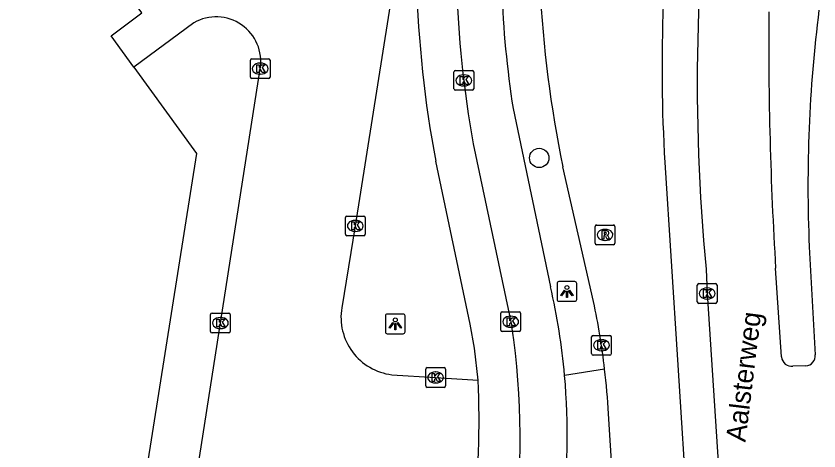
# Model space of a CAD drawing. Extents: x 161094 to 161705, y 379509 to 380907.
# Drawn here: x 161646.2 to 161686.89, y 380754.87 to 380776.91 of the extents above; entities that cross this region are included whole.
import ezdxf

# ---------------------------------------------------------------- set-up
doc = ezdxf.new("R2010")
doc.units = 0
for name, color, linetype in [('IMGEO_Boom', 7, 'Continuous'), ('IMGEO_Fietspad_gesloten', 7, 'Continuous'), ('IMGEO_Kolk', 7, 'Continuous'), ('IMGEO_Lichtpunt', 7, 'Continuous'), ('IMGEO_Openbare_ruimte_label', 7, 'Continuous'), ('IMGEO_OVBaan_gesloten', 7, 'Continuous'), ('IMGEO_Pand', 7, 'Continuous'), ('IMGEO_Rijbaan_lokaal_open', 7, 'Continuous'), ('IMGEO_Rijbaan_regionaal_gesloten', 7, 'Continuous'), ('IMGEO_Rioolput', 7, 'Continuous'), ('IMGEO_Voetpad_open', 7, 'Continuous')]:
    doc.layers.add(name, color=color, linetype=linetype)

msp = doc.modelspace()

# ---------------------------------------------------------------- linework, layer by layer
at = {"layer": 'IMGEO_Boom'}
msp.add_circle((161672.711, 380769.715), 0.489, dxfattribs=at)
at = {"layer": 'IMGEO_Fietspad_gesloten'}
for points in [[(161671.386, 380772.223), (161673.279, 380763.191)], [(161669.37, 380770.437), (161671.328, 380761.181)]]:
    msp.add_lwpolyline(points, dxfattribs=at)
for centre, radius, start, end in [((161723.373, 380780.209), 54.88, 173.1036, 190.2571), ((161721.642, 380780.053), 50.862, 175.2018, 188.8552), ((161641.134, 380755.741), 32.997, 5.1467, 13.0487), ((161633.879, 380755.588), 37.865, 351.9368, 8.4941)]:
    msp.add_arc(centre, radius, start, end, dxfattribs=at)
at = {"layer": 'IMGEO_Kolk'}
for p, q in [((161658.072, 380773.816), (161658.072, 380774.668)), ((161658.147, 380774.742), (161658.999, 380774.742)), ((161659.073, 380774.668), (161659.073, 380773.816)), ((161658.56, 380774.522), (161658.585, 380774.522)), ((161658.583, 380773.962), (161658.558, 380773.962)), ((161668.392, 380773.22), (161668.392, 380774.072)), ((161668.467, 380774.146), (161669.319, 380774.146)), ((161668.88, 380773.926), (161668.905, 380773.926)), ((161669.393, 380774.072), (161669.393, 380773.22)), ((161658.999, 380773.742), (161658.147, 380773.742)), ((161668.903, 380773.366), (161668.878, 380773.366)), ((161669.319, 380773.146), (161668.467, 380773.146)), ((161662.889, 380765.848), (161662.889, 380766.7)), ((161662.964, 380766.774), (161663.816, 380766.774)), ((161663.377, 380766.554), (161663.402, 380766.554)), ((161663.89, 380766.7), (161663.89, 380765.848)), ((161663.816, 380765.774), (161662.964, 380765.774)), ((161663.4, 380765.994), (161663.375, 380765.994)), ((161680.721, 380762.422), (161680.721, 380763.274)), ((161680.796, 380763.348), (161681.648, 380763.348)), ((161681.722, 380763.274), (161681.722, 380762.422)), ((161681.209, 380763.128), (161681.234, 380763.128)), ((161681.232, 380762.568), (161681.207, 380762.568)), ((161681.648, 380762.348), (161680.796, 380762.348)), ((161656.054, 380760.926), (161656.054, 380761.778)), ((161656.129, 380761.852), (161656.981, 380761.852)), ((161656.542, 380761.632), (161656.567, 380761.632)), ((161657.055, 380761.778), (161657.055, 380760.926)), ((161670.764, 380760.992), (161670.764, 380761.844)), ((161670.839, 380761.918), (161671.691, 380761.918)), ((161671.252, 380761.698), (161671.277, 380761.698)), ((161671.765, 380761.844), (161671.765, 380760.992)), ((161671.275, 380761.138), (161671.25, 380761.138)), ((161656.981, 380760.852), (161656.129, 380760.852)), ((161656.565, 380761.072), (161656.54, 380761.072)), ((161671.691, 380760.918), (161670.839, 380760.918)), ((161675.439, 380760.727), (161676.291, 380760.727)), ((161675.364, 380759.801), (161675.364, 380760.653)), ((161675.852, 380760.507), (161675.877, 380760.507)), ((161676.365, 380760.653), (161676.365, 380759.801)), ((161675.875, 380759.947), (161675.85, 380759.947)), ((161676.291, 380759.727), (161675.439, 380759.727)), ((161666.961, 380758.168), (161666.961, 380759.02)), ((161667.036, 380759.094), (161667.888, 380759.094)), ((161667.449, 380758.874), (161667.474, 380758.874)), ((161667.962, 380759.02), (161667.962, 380758.168)), ((161667.472, 380758.314), (161667.447, 380758.314)), ((161667.888, 380758.094), (161667.036, 380758.094))]:
    msp.add_line(p, q, dxfattribs=at)
for points in [[(161658.072, 380773.816), (161658.072, 380774.668)], [(161658.147, 380774.742), (161658.999, 380774.742)], [(161659.073, 380774.668), (161659.073, 380773.816)], [(161658.393, 380774.442), (161658.516, 380774.442), (161658.516, 380774.291), (161658.646, 380774.442), (161658.81, 380774.442), (161658.664, 380774.291), (161658.817, 380774.042), (161658.665, 380774.042), (161658.58, 380774.206), (161658.516, 380774.139), (161658.516, 380774.042), (161658.393, 380774.042), (161658.393, 380774.442)], [(161668.392, 380773.22), (161668.392, 380774.072)], [(161668.467, 380774.146), (161669.319, 380774.146)], [(161668.713, 380773.846), (161668.836, 380773.846), (161668.836, 380773.695), (161668.966, 380773.846), (161669.13, 380773.846), (161668.984, 380773.695), (161669.137, 380773.446), (161668.985, 380773.446), (161668.9, 380773.61), (161668.836, 380773.543), (161668.836, 380773.446), (161668.713, 380773.446), (161668.713, 380773.846)], [(161669.393, 380774.072), (161669.393, 380773.22)], [(161658.999, 380773.742), (161658.147, 380773.742)], [(161669.319, 380773.146), (161668.467, 380773.146)], [(161662.889, 380765.848), (161662.889, 380766.7)], [(161662.964, 380766.774), (161663.816, 380766.774)], [(161663.21, 380766.474), (161663.333, 380766.474), (161663.333, 380766.323), (161663.463, 380766.474), (161663.627, 380766.474), (161663.481, 380766.323), (161663.634, 380766.074), (161663.482, 380766.074), (161663.397, 380766.238), (161663.333, 380766.171), (161663.333, 380766.074), (161663.21, 380766.074), (161663.21, 380766.474)], [(161663.89, 380766.7), (161663.89, 380765.848)], [(161663.816, 380765.774), (161662.964, 380765.774)], [(161680.721, 380762.422), (161680.721, 380763.274)], [(161680.796, 380763.348), (161681.648, 380763.348)], [(161681.722, 380763.274), (161681.722, 380762.422)], [(161681.042, 380763.048), (161681.165, 380763.048), (161681.165, 380762.897), (161681.295, 380763.048), (161681.459, 380763.048), (161681.313, 380762.897), (161681.466, 380762.648), (161681.314, 380762.648), (161681.229, 380762.812), (161681.165, 380762.745), (161681.165, 380762.648), (161681.042, 380762.648), (161681.042, 380763.048)], [(161681.648, 380762.348), (161680.796, 380762.348)], [(161656.054, 380760.926), (161656.054, 380761.778)], [(161656.129, 380761.852), (161656.981, 380761.852)], [(161656.375, 380761.552), (161656.498, 380761.552), (161656.498, 380761.401), (161656.628, 380761.552), (161656.792, 380761.552), (161656.646, 380761.401), (161656.799, 380761.152), (161656.647, 380761.152), (161656.562, 380761.316), (161656.498, 380761.249), (161656.498, 380761.152), (161656.375, 380761.152), (161656.375, 380761.552)], [(161657.055, 380761.778), (161657.055, 380760.926)], [(161670.764, 380760.992), (161670.764, 380761.844)], [(161670.839, 380761.918), (161671.691, 380761.918)], [(161671.085, 380761.618), (161671.208, 380761.618), (161671.208, 380761.467), (161671.338, 380761.618), (161671.502, 380761.618), (161671.356, 380761.467), (161671.509, 380761.218), (161671.357, 380761.218), (161671.272, 380761.382), (161671.208, 380761.315), (161671.208, 380761.218), (161671.085, 380761.218), (161671.085, 380761.618)], [(161671.765, 380761.844), (161671.765, 380760.992)], [(161656.981, 380760.852), (161656.129, 380760.852)], [(161671.691, 380760.918), (161670.839, 380760.918)], [(161675.439, 380760.727), (161676.291, 380760.727)], [(161675.364, 380759.801), (161675.364, 380760.653)], [(161675.685, 380760.427), (161675.808, 380760.427), (161675.808, 380760.276), (161675.938, 380760.427), (161676.102, 380760.427), (161675.956, 380760.276), (161676.109, 380760.027), (161675.957, 380760.027), (161675.872, 380760.191), (161675.808, 380760.124), (161675.808, 380760.027), (161675.685, 380760.027), (161675.685, 380760.427)], [(161676.365, 380760.653), (161676.365, 380759.801)], [(161676.291, 380759.727), (161675.439, 380759.727)], [(161666.961, 380758.168), (161666.961, 380759.02)], [(161667.036, 380759.094), (161667.888, 380759.094)], [(161667.282, 380758.794), (161667.405, 380758.794), (161667.405, 380758.643), (161667.535, 380758.794), (161667.699, 380758.794), (161667.553, 380758.643), (161667.706, 380758.394), (161667.554, 380758.394), (161667.469, 380758.558), (161667.405, 380758.491), (161667.405, 380758.394), (161667.282, 380758.394), (161667.282, 380758.794)], [(161667.962, 380759.02), (161667.962, 380758.168)], [(161667.888, 380758.094), (161667.036, 380758.094)]]:
    msp.add_lwpolyline(points, dxfattribs=at)
for centre, start, end in [((161658.149, 380774.666), 91.552, 178.448), ((161658.149, 380774.666), 91.552, 178.448), ((161658.997, 380774.666), 1.552, 88.448), ((161658.997, 380774.666), 1.552, 88.448), ((161658.149, 380773.818), 181.552, 268.448), ((161658.149, 380773.818), 181.552, 268.448), ((161658.997, 380773.818), 271.552, 358.448), ((161658.997, 380773.818), 271.552, 358.448), ((161668.469, 380774.07), 91.552, 178.448), ((161668.469, 380774.07), 91.552, 178.448), ((161669.317, 380774.07), 1.552, 88.448), ((161669.317, 380774.07), 1.552, 88.448), ((161668.469, 380773.222), 181.552, 268.448), ((161668.469, 380773.222), 181.552, 268.448), ((161669.317, 380773.222), 271.552, 358.448), ((161669.317, 380773.222), 271.552, 358.448), ((161662.966, 380766.698), 91.552, 178.448), ((161662.966, 380766.698), 91.552, 178.448), ((161663.814, 380766.698), 1.552, 88.448), ((161663.814, 380766.698), 1.552, 88.448), ((161662.966, 380765.85), 181.552, 268.448), ((161662.966, 380765.85), 181.552, 268.448), ((161663.814, 380765.85), 271.552, 358.448), ((161663.814, 380765.85), 271.552, 358.448), ((161680.798, 380763.272), 91.552, 178.448), ((161680.798, 380763.272), 91.552, 178.448), ((161681.646, 380763.272), 1.552, 88.448), ((161681.646, 380763.272), 1.552, 88.448), ((161680.798, 380762.424), 181.552, 268.448), ((161680.798, 380762.424), 181.552, 268.448), ((161681.646, 380762.424), 271.552, 358.448), ((161681.646, 380762.424), 271.552, 358.448), ((161656.131, 380761.776), 91.552, 178.448), ((161656.131, 380761.776), 91.552, 178.448), ((161656.979, 380761.776), 1.552, 88.448), ((161656.979, 380761.776), 1.552, 88.448), ((161670.841, 380761.842), 91.552, 178.448), ((161670.841, 380761.842), 91.552, 178.448), ((161671.689, 380761.842), 1.552, 88.448), ((161671.689, 380761.842), 1.552, 88.448), ((161656.131, 380760.928), 181.552, 268.448), ((161656.131, 380760.928), 181.552, 268.448), ((161656.979, 380760.928), 271.552, 358.448), ((161656.979, 380760.928), 271.552, 358.448), ((161670.841, 380760.994), 181.552, 268.448), ((161670.841, 380760.994), 181.552, 268.448), ((161671.689, 380760.994), 271.552, 358.448), ((161671.689, 380760.994), 271.552, 358.448), ((161675.441, 380760.651), 91.552, 178.448), ((161675.441, 380760.651), 91.552, 178.448), ((161676.289, 380760.651), 1.552, 88.448), ((161676.289, 380760.651), 1.552, 88.448), ((161675.441, 380759.803), 181.552, 268.448), ((161675.441, 380759.803), 181.552, 268.448), ((161676.289, 380759.803), 271.552, 358.448), ((161676.289, 380759.803), 271.552, 358.448), ((161667.038, 380759.018), 91.552, 178.448), ((161667.038, 380759.018), 91.552, 178.448), ((161667.886, 380759.018), 1.552, 88.448), ((161667.886, 380759.018), 1.552, 88.448), ((161667.038, 380758.17), 181.552, 268.448), ((161667.038, 380758.17), 181.552, 268.448), ((161667.886, 380758.17), 271.552, 358.448), ((161667.886, 380758.17), 271.552, 358.448)]:
    msp.add_arc(centre, 0.0765, start, end, dxfattribs=at)
for centre, major_axis, ratio, start_param, end_param in [((161658.559, 380774.242), (-0.387, 0.002), 0.722429, 4.712389, 7.853982), ((161658.584, 380774.242), (-0.39, 0.002), 0.717154, 1.570796, 4.712389), ((161668.879, 380773.646), (-0.387, 0.002), 0.722429, 4.712389, 7.853982), ((161668.904, 380773.646), (-0.39, 0.002), 0.717154, 1.570796, 4.712389), ((161663.376, 380766.274), (-0.387, 0.002), 0.722429, 4.712389, 7.853982), ((161663.401, 380766.274), (-0.39, 0.002), 0.717154, 1.570796, 4.712389), ((161681.208, 380762.848), (-0.387, 0.002), 0.722429, 4.712389, 7.853982), ((161681.233, 380762.848), (-0.39, 0.002), 0.717154, 1.570796, 4.712389), ((161656.541, 380761.352), (-0.387, 0.002), 0.722429, 4.712389, 7.853982), ((161656.566, 380761.352), (-0.39, 0.002), 0.717154, 1.570796, 4.712389), ((161671.251, 380761.418), (-0.387, 0.002), 0.722429, 4.712389, 7.853982), ((161671.276, 380761.418), (-0.39, 0.002), 0.717154, 1.570796, 4.712389), ((161675.851, 380760.227), (-0.387, 0.002), 0.722429, 4.712389, 7.853982), ((161675.876, 380760.227), (-0.39, 0.002), 0.717154, 1.570796, 4.712389), ((161667.448, 380758.594), (-0.387, 0.002), 0.722429, 4.712389, 7.853982), ((161667.473, 380758.594), (-0.39, 0.002), 0.717154, 1.570796, 4.712389)]:
    msp.add_ellipse(centre, major_axis=major_axis, ratio=ratio, start_param=start_param, end_param=end_param, dxfattribs=at)
at = {"layer": 'IMGEO_Lichtpunt'}
for p, q in [((161673.615, 380763.354), (161673.615, 380762.547)), ((161673.615, 380763.354), (161673.615, 380762.547)), ((161674.517, 380763.449), (161673.709, 380763.449)), ((161674.517, 380763.449), (161673.709, 380763.449)), ((161674.611, 380762.547), (161674.611, 380763.354)), ((161674.611, 380762.547), (161674.611, 380763.354)), ((161673.709, 380762.453), (161674.517, 380762.453)), ((161673.709, 380762.453), (161674.517, 380762.453)), ((161664.919, 380761.712), (161664.919, 380760.905)), ((161664.919, 380761.712), (161664.919, 380760.905)), ((161665.821, 380761.807), (161665.013, 380761.807)), ((161665.821, 380761.807), (161665.013, 380761.807)), ((161665.915, 380760.905), (161665.915, 380761.712)), ((161665.915, 380760.905), (161665.915, 380761.712)), ((161665.013, 380760.811), (161665.821, 380760.811)), ((161665.013, 380760.811), (161665.821, 380760.811))]:
    msp.add_line(p, q, dxfattribs=at)
for points in [[(161673.989, 380763.018), (161674.028, 380762.99), (161673.84, 380762.728), (161673.802, 380762.755), (161673.989, 380763.018)], [(161674.091, 380762.97), (161674.138, 380762.97), (161674.138, 380762.648), (161674.091, 380762.648), (161674.091, 380762.97)], [(161674.201, 380762.99), (161674.239, 380763.017), (161674.426, 380762.755), (161674.387, 380762.727), (161674.201, 380762.99)], [(161665.293, 380761.376), (161665.332, 380761.348), (161665.144, 380761.086), (161665.106, 380761.113), (161665.293, 380761.376)], [(161665.395, 380761.328), (161665.442, 380761.328), (161665.442, 380761.006), (161665.395, 380761.006), (161665.395, 380761.328)], [(161665.505, 380761.348), (161665.543, 380761.375), (161665.73, 380761.113), (161665.691, 380761.085), (161665.505, 380761.348)]]:
    msp.add_lwpolyline(points, dxfattribs=at)
for centre in [(161674.114, 380763.152), (161665.418, 380761.51)]:
    msp.add_circle(centre, 0.0994, dxfattribs=at)
for centre, start, end in [((161673.709, 380763.354), 90, 180), ((161673.709, 380763.354), 90, 180), ((161674.517, 380763.354), 0, 90), ((161674.517, 380763.354), 0, 90), ((161673.709, 380762.547), 180, 270), ((161673.709, 380762.547), 180, 270), ((161674.517, 380762.547), 270, 0), ((161674.517, 380762.547), 270, 360), ((161665.013, 380761.712), 90, 180), ((161665.013, 380761.712), 90, 180), ((161665.821, 380761.712), 0, 90), ((161665.821, 380761.712), 0, 90), ((161665.013, 380760.905), 180, 270), ((161665.013, 380760.905), 180, 270), ((161665.821, 380760.905), 270, 0), ((161665.821, 380760.905), 270, 360)]:
    msp.add_arc(centre, 0.0946, start, end, dxfattribs=at)
at = {"layer": 'IMGEO_OVBaan_gesloten'}
for points in [[(161679.076, 380769.48), (161679.713, 380759.482), (161680.24, 380751.239)], [(161675.461, 380762.437), (161673.908, 380769.269)], [(161676.761, 380747.77), (161676.717, 380749.003), (161676.218, 380756.754)]]:
    msp.add_lwpolyline(points, dxfattribs=at)
for centre, radius, start, end in [((161760.684, 380774.29), 81.75, 172.12146, 183.37333), ((161732.697, 380781.403), 60.028, 182.86621, 191.66173), ((161640.216, 380754.852), 36.052, 6.6276, 12.1451), ((161639.684, 380754.803), 36.586, 3.0574, 6.6084)]:
    msp.add_arc(centre, radius, start, end, dxfattribs=at)
at = {"layer": 'IMGEO_Pand'}
for points in [[(161652.167, 380774.32), (161651.017, 380775.909), (161652.573, 380777.061), (161651.743, 380778.194), (161652.429, 380778.714), (161650.668, 380781.143), (161649.954, 380780.648), (161649.119, 380781.768), (161647.581, 380780.621), (161646.411, 380782.235)], [(161652.167, 380774.32), (161655.336, 380769.945), (161652.191, 380750), (161651.629, 380746.437), (161648.267, 380746.956), (161647.471, 380741.727), (161647.355, 380741.635), (161645.817, 380741.887)]]:
    msp.add_lwpolyline(points, dxfattribs=at)
at = {"layer": 'IMGEO_Rijbaan_lokaal_open'}
for points in [[(161665.659, 380780.797), (161665.645, 380780.589), (161663.39, 380766.274), (161662.705, 380762.13)], [(161655.209, 380776.564), (161652.167, 380774.32)], [(161654.446, 380747.932), (161654.778, 380750), (161658.575, 380774.236)], [(161665.24, 380758.734), (161667.462, 380758.594), (161669.617, 380758.465)], [(161676.027, 380759.013), (161673.998, 380758.701)]]:
    msp.add_lwpolyline(points, dxfattribs=at)
for centre, radius, start, end in [((161656.334, 380774.593), 2.27, 350.9594, 119.7034), ((161665.598, 380761.646), 2.933, 170.4933, 262.9869), ((161641.27, 380755.754), 32.86, 352.1827, 5.1446), ((161620.619, 380756.365), 49.043, 353.974, 2.4546)]:
    msp.add_arc(centre, radius, start, end, dxfattribs=at)
at = {"layer": 'IMGEO_Rijbaan_regionaal_gesloten'}
for points in [[(161686.397, 380765.221), (161686.702, 380759.742)], [(161681.167, 380764.087), (161681.222, 380762.848), (161682.348, 380745.495), (161682.847, 380736.944), (161683.075, 380733.314)], [(161684.993, 380759.631), (161684.691, 380764.131)], [(161686.225, 380759.187), (161685.568, 380759.163)]]:
    msp.add_lwpolyline(points, dxfattribs=at)
for centre, radius, start, end in [((161779.873, 380773.521), 99.156, 172.04216, 185.4598), ((161871.342, 380775.531), 186.999, 179.51098, 183.49508), ((161757.107, 380768.335), 70.778, 172.80356, 182.52203), ((161685.505, 380759.673), 0.514, 184.6469, 277.0679), ((161686.202, 380759.689), 0.502, 272.5747, 6.0699)]:
    msp.add_arc(centre, radius, start, end, dxfattribs=at)
at = {"layer": 'IMGEO_Rioolput'}
for p, q in [((161675.544, 380765.393), (161675.544, 380766.245)), ((161675.619, 380766.319), (161676.471, 380766.319)), ((161676.032, 380766.099), (161676.057, 380766.099)), ((161676.545, 380766.245), (161676.545, 380765.393)), ((161676.471, 380765.319), (161675.619, 380765.319)), ((161676.055, 380765.539), (161676.03, 380765.539))]:
    msp.add_line(p, q, dxfattribs=at)
for points in [[(161675.544, 380765.393), (161675.544, 380766.245)], [(161675.619, 380766.319), (161676.471, 380766.319)], [(161676.133, 380766.017), (161675.881, 380766.019), (161675.881, 380765.619)], [(161676.545, 380766.245), (161676.545, 380765.393)], [(161675.881, 380765.619), (161676.005, 380765.619), (161676.005, 380765.781), (161676.016, 380765.781)], [(161676.059, 380765.938), (161676.005, 380765.938), (161676.005, 380765.857)], [(161676.005, 380765.857), (161676.057, 380765.857)], [(161676.063, 380765.752), (161676.134, 380765.619), (161676.274, 380765.619), (161676.209, 380765.745)], [(161676.471, 380765.319), (161675.619, 380765.319)]]:
    msp.add_lwpolyline(points, dxfattribs=at)
for centre, radius, start, end in [((161675.621, 380766.243), 0.0765, 91.552, 178.448), ((161675.621, 380766.243), 0.0765, 91.552, 178.448), ((161676.132, 380765.907), 0.109, 350.3612, 89.416), ((161676.469, 380766.243), 0.0765, 1.552, 88.448), ((161676.469, 380766.243), 0.0765, 1.552, 88.448), ((161676.015, 380765.728), 0.0533, 26.0293, 88.6989), ((161676.041, 380766.046), 0.19, 274.7715, 282.9687), ((161676.065, 380765.842), 0.0964, 77.0061, 93.1865), ((161676.079, 380765.899), 0.0378, 276.6634, 79.6772), ((161676.13, 380765.907), 0.112, 277.5842, 350.9817), ((161676.114, 380765.692), 0.108, 29.5134, 73.7905), ((161675.621, 380765.395), 0.0765, 181.552, 268.448), ((161675.621, 380765.395), 0.0765, 181.552, 268.448), ((161676.469, 380765.395), 0.0765, 271.552, 358.448), ((161676.469, 380765.395), 0.0765, 271.552, 358.448)]:
    msp.add_arc(centre, radius, start, end, dxfattribs=at)
for centre, major_axis, ratio, start_param, end_param in [((161676.031, 380765.819), (-0.387, 0.002), 0.722429, 4.712389, 7.853982), ((161676.056, 380765.819), (-0.39, 0.002), 0.717154, 1.570796, 4.712389)]:
    msp.add_ellipse(centre, major_axis=major_axis, ratio=ratio, start_param=start_param, end_param=end_param, dxfattribs=at)
at = {"layer": 'IMGEO_Voetpad_open'}
msp.add_lwpolyline([(161669.617, 380758.465), (161669.424, 380760.076), (161669.211, 380761.293), (161667.469, 380769.554)], dxfattribs=at)
msp.add_arc((161723.86, 380780.217), 57.391, 172.42154, 190.70771, dxfattribs=at)

# ---------------------------------------------------------------- texts
at = {"layer": 'IMGEO_Openbare_ruimte_label'}
msp.add_text('Aalsterweg', height=1, rotation=82.9957, dxfattribs=at).set_placement((161683.158, 380755.291))

doc.saveas('drawing.dxf')
